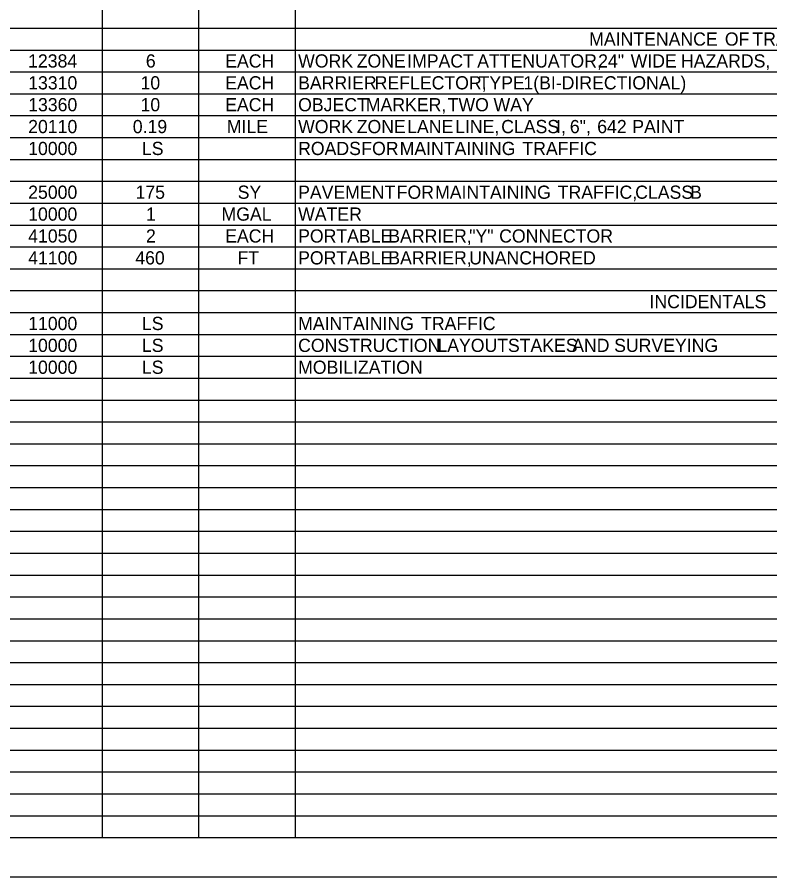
# Model space of a CAD drawing. Extents: x 0 to 34, y 0 to 22.
# Drawn here: x 16.94 to 26.57, y 0 to 11 of the extents above; entities that cross this region are included whole.
import ezdxf

# ---------------------------------------------------------------- set-up
doc = ezdxf.new("R2010")
doc.units = 0
for name, color, linetype in [('SH_Border', 7, 'Continuous'), ('SH_Cut_Line', 7, 'Continuous'), ('SH_Data', 7, 'Continuous')]:
    doc.layers.add(name, color=color, linetype=linetype)

msp = doc.modelspace()

# ---------------------------------------------------------------- linework, layer by layer
at = {"layer": 'SH_Border'}
msp.add_lwpolyline([(1.5, 21.5), (33.5, 21.5), (33.5, 0.5), (1.5, 0.5)], close=True, dxfattribs=at)
at = {"layer": 'SH_Cut_Line'}
msp.add_lwpolyline([(0, 0), (34, 0), (34, 22), (0, 22)], close=True, dxfattribs=at)
at = {"layer": 'SH_Data'}
for p, q in [((18.035, 0.502), (18.035, 21.5)), ((19.27, 0.502), (19.27, 21.5)), ((20.505, 0.502), (20.505, 21.5)), ((1.5, 10.861), (32, 10.861)), ((1.5, 10.581), (32, 10.581)), ((1.5, 10.301), (32, 10.301)), ((1.5, 10.021), (32, 10.021)), ((1.5, 9.741), (32, 9.741)), ((1.5, 9.461), (32, 9.461)), ((1.5, 9.181), (32, 9.181)), ((1.5, 8.901), (32, 8.901)), ((1.5, 8.621), (32, 8.621)), ((1.5, 8.341), (32, 8.341)), ((1.5, 8.062), (32, 8.062)), ((1.5, 7.782), (32, 7.782)), ((1.5, 7.502), (32, 7.502)), ((1.5, 7.222), (32, 7.222)), ((1.5, 6.942), (32, 6.942)), ((1.5, 6.662), (32, 6.662)), ((1.5, 6.382), (32, 6.382)), ((1.5, 6.102), (32, 6.102)), ((1.5, 5.822), (32, 5.822)), ((1.5, 5.542), (32, 5.542)), ((1.5, 5.262), (32, 5.262)), ((1.5, 4.982), (32, 4.982)), ((1.5, 4.702), (32, 4.702)), ((1.5, 4.422), (32, 4.422)), ((1.5, 4.142), (32, 4.142)), ((1.5, 3.862), (32, 3.862)), ((1.5, 3.582), (32, 3.582)), ((1.5, 3.302), (32, 3.302)), ((1.5, 3.022), (32, 3.022)), ((1.5, 2.742), (32, 2.742)), ((1.5, 2.462), (32, 2.462)), ((1.5, 2.182), (32, 2.182)), ((1.5, 1.902), (32, 1.902)), ((1.5, 1.622), (32, 1.622)), ((1.5, 1.342), (32, 1.342)), ((1.5, 1.062), (32, 1.062)), ((1.5, 0.782), (32, 0.782)), ((1.5, 0.502), (32, 0.502))]:
    msp.add_line(p, q, dxfattribs=at)

# ---------------------------------------------------------------- texts
for s, height, p in [('MAINTENANCE', 0.16891, (24.261, 10.637)), (' OF', 0.1689, (25.934, 10.637)), (' TRAFFIC', 0.1689, (26.286, 10.637)), ('12384', 0.1689, (17.084, 10.357)), ('6', 0.169, (18.59, 10.357)), ('EACH', 0.1689, (19.605, 10.357)), ('WORK', 0.1689, (20.538, 10.357)), (' ZONE', 0.1689, (21.225, 10.357)), (' IMPACT', 0.1689, (21.87, 10.357)), (' ATTENUATOR,', 0.16891, (22.766, 10.357)), (' 24"', 0.1689, (24.313, 10.357)), (' WIDE', 0.1689, (24.729, 10.357)), (' HAZARDS,', 0.1689, (25.373, 10.357)), ('13310', 0.1689, (17.085, 10.077)), ('10', 0.1689, (18.522, 10.077)), ('EACH', 0.1689, (19.605, 10.077)), ('BARRIER', 0.1689, (20.538, 10.077)), (' REFLECTOR,', 0.16891, (21.455, 10.077)), (' TYPE', 0.1689, (22.784, 10.077)), (' 1(BI-DIRECTIONAL)', 0.16891, (23.357, 10.077)), ('13360', 0.1689, (17.085, 9.797)), ('10', 0.1689, (18.522, 9.797)), ('EACH', 0.1689, (19.605, 9.797)), ('OBJECT', 0.1689, (20.538, 9.797)), (' MARKER,', 0.1689, (21.341, 9.797)), (' TWO', 0.1689, (22.388, 9.797)), (' WAY', 0.1689, (22.975, 9.797)), ('20110', 0.1689, (17.085, 9.517)), ('0.19', 0.1689, (18.423, 9.517)), ('MILE', 0.1689, (19.626, 9.517)), ('WORK', 0.1689, (20.538, 9.517)), (' ZONE', 0.1689, (21.225, 9.517)), (' LANE', 0.1689, (21.87, 9.517)), (' LINE,', 0.1689, (22.484, 9.517)), (' CLASS', 0.1689, (23.073, 9.517)), (' I,', 0.1689, (23.775, 9.517)), (' 6",', 0.1689, (23.951, 9.517)), (' 642', 0.1689, (24.301, 9.517)), (' PAINT', 0.1689, (24.75, 9.517)), ('10000', 0.1689, (17.085, 9.237)), ('LS', 0.1689, (18.54, 9.237)), ('ROADS', 0.1689, (20.538, 9.237)), (' FOR', 0.1689, (21.283, 9.237)), (' MAINTAINING', 0.16891, (21.774, 9.237)), (' TRAFFIC', 0.1689, (23.344, 9.237)), ('25000', 0.1689, (17.085, 8.677)), ('175', 0.1689, (18.458, 8.677)), ('SY', 0.1689, (19.765, 8.677)), ('PAVEMENT', 0.1689, (20.538, 8.677)), (' FOR', 0.1689, (21.736, 8.677)), (' MAINTAINING', 0.16891, (22.227, 8.677)), (' TRAFFIC,', 0.1689, (23.796, 8.677)), (' CLASS', 0.1689, (24.787, 8.677)), (' B', 0.1689, (25.489, 8.677)), ('10000', 0.1689, (17.085, 8.397)), ('1', 0.169, (18.592, 8.397)), ('MGAL', 0.1689, (19.558, 8.397)), ('WATER', 0.1689, (20.538, 8.397)), ('41050', 0.1689, (17.085, 8.117)), ('2', 0.169, (18.592, 8.117)), ('EACH', 0.1689, (19.605, 8.117)), ('PORTABLE', 0.1689, (20.538, 8.117)), (' BARRIER,', 0.1689, (21.629, 8.117)), (' "Y"', 0.1689, (22.664, 8.117)), (' CONNECTOR', 0.1689, (23.047, 8.117)), ('41100', 0.1689, (17.085, 7.837)), ('460', 0.1689, (18.455, 7.837)), ('FT', 0.1689, (19.762, 7.837)), ('PORTABLE', 0.1689, (20.538, 7.837)), (' BARRIER,', 0.1689, (21.629, 7.837)), (' UNANCHORED', 0.16891, (22.664, 7.837)), ('INCIDENTALS', 0.16891, (25.033, 7.277)), ('11000', 0.1689, (17.085, 6.997)), ('LS', 0.1689, (18.54, 6.997)), ('MAINTAINING', 0.16891, (20.538, 6.997)), (' TRAFFIC', 0.1689, (22.048, 6.997)), ('10000', 0.1689, (17.085, 6.717)), ('LS', 0.1689, (18.54, 6.717)), ('CONSTRUCTION', 0.16891, (20.538, 6.717)), (' LAYOUT', 0.1689, (22.257, 6.717)), (' STAKES', 0.1689, (23.159, 6.717)), (' AND', 0.1689, (23.981, 6.717)), (' SURVEYING', 0.1689, (24.518, 6.717)), ('10000', 0.1689, (17.085, 6.437)), ('LS', 0.1689, (18.54, 6.437)), ('MOBILIZATION', 0.16891, (20.538, 6.437))]:
    msp.add_text(s, height=height, dxfattribs=at).set_placement(p)

doc.saveas('drawing.dxf')
